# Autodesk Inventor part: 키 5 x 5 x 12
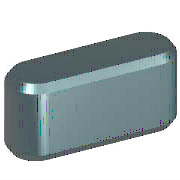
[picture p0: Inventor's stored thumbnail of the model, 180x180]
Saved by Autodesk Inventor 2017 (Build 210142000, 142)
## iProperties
IsCustomPart: 1
Created: 2012-02
Part Number: 키 5 x 5 x 12
Material: 강철, 연강
Description: 키 및 해당 키홈
Document SubType Name: Modeling
Standard: KS B 1311
Designer: mduedu
Standards Organization: KS
Language: ko-KR
Size Designation: 5 x 5 x 12
Categories: <MemberInstance><Categories><Category DisplayName="샤프트 부품" InternalName="7f7aeb1f-a693-4053-b835-cee3144e0d98" Mnemonic="SHFT"><Category DisplayName="키" Interna
Density: 7.86 g/cm^3
Mass: 2.11085 g
Surface Area: 2.43471 cm^2
Volume: 0.268556 cm^3
Appearance: 노란색
Author: mduedu
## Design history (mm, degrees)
workplane "Work Plane1"
workplane "Work Plane2"
sketch "스케치1"
  geometry: L1 (2.5, 2.5)-(9.5, 2.5); L2 (9.5, -2.5)-(2.5, -2.5); L3 (0, 9.4)-(0, -7.4) reference; L4 (-5, 0)-(30, 0) reference; L5 (12, 0)-(12, 7); A1 r 2.5 centre (2.5, 0) between (2.5, 2.5) and (2.5, -2.5); A2 r 2.5 centre (9.5, 0) between (9.5, -2.5) and (9.5, 2.5)
  constraints: 6 end point, 5 point on circle, 4 tangent, 3 point on line, 2 centre point, 1 horizontal, 1 parallel, 1 perpendicular
  dimensions: "d0" = 2.5 radius of A1 (= 0.5 x PB); "d13" = 2.5 radius of A2 (= 0.5 x PB); "d14" = 12 distance between parallel lines of L5 L3 (= NLG)
extrude "본체1" new body sketch "스케치1" taper "d3" = 0 deg; stored distance "d4" = 10
workplane "Work Plane3"
body "Solid1"
chamfer "모따기1" distance "d8" = 0.4 (= PHH); stored, may be unused: second distance "d9" = 0.4 (= PHH), angle "d15" = 45 deg
other parameters: "d1" = -3 (= -PNT), "d2" = 2 (= PH - PNT), "NLG" = 12 [user parameter; used in 3 equation terms], "PB" = 5 [user parameter; used in 2 equation terms], "PNT" = 3 [user parameter; used in 2 equation terms], "PH" = 5 [user parameter; used in 1 equation term], "PHH" = 0.4 [user parameter; used in 2 equation terms], "d10" = 0, "d16" = 0, "d17" = 0, "d18" = 0, "WDMIN" = 12 [user parameter], "PLB2" = 12 (= NLG) [user parameter], "WDMAX" = 17 [user parameter], "PLB1" = 12 (= NLG) [user parameter], "RR" = 0.16 [user parameter], "PUEB" = 2.3 [user parameter]
